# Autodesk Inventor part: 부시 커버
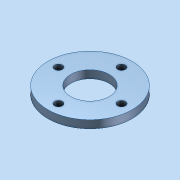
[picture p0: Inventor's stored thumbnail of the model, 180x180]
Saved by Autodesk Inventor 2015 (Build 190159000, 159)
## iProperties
Created: 2024-06
Part Number: 부시 커버
Material: 일반
Document SubType Name: Modeling
Designer: Administrator
Density: 1 g/cm^3
Appearance: 기본값
Author: Administrator
Author: jhkim
Creation Date: 2024-05-29
Sending System: Autodesk Inventor 2025
Preprocessor: ST-DEVELOPER v20
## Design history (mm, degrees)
node "부시 커버1"
node "솔리드1"
node "기준1"
